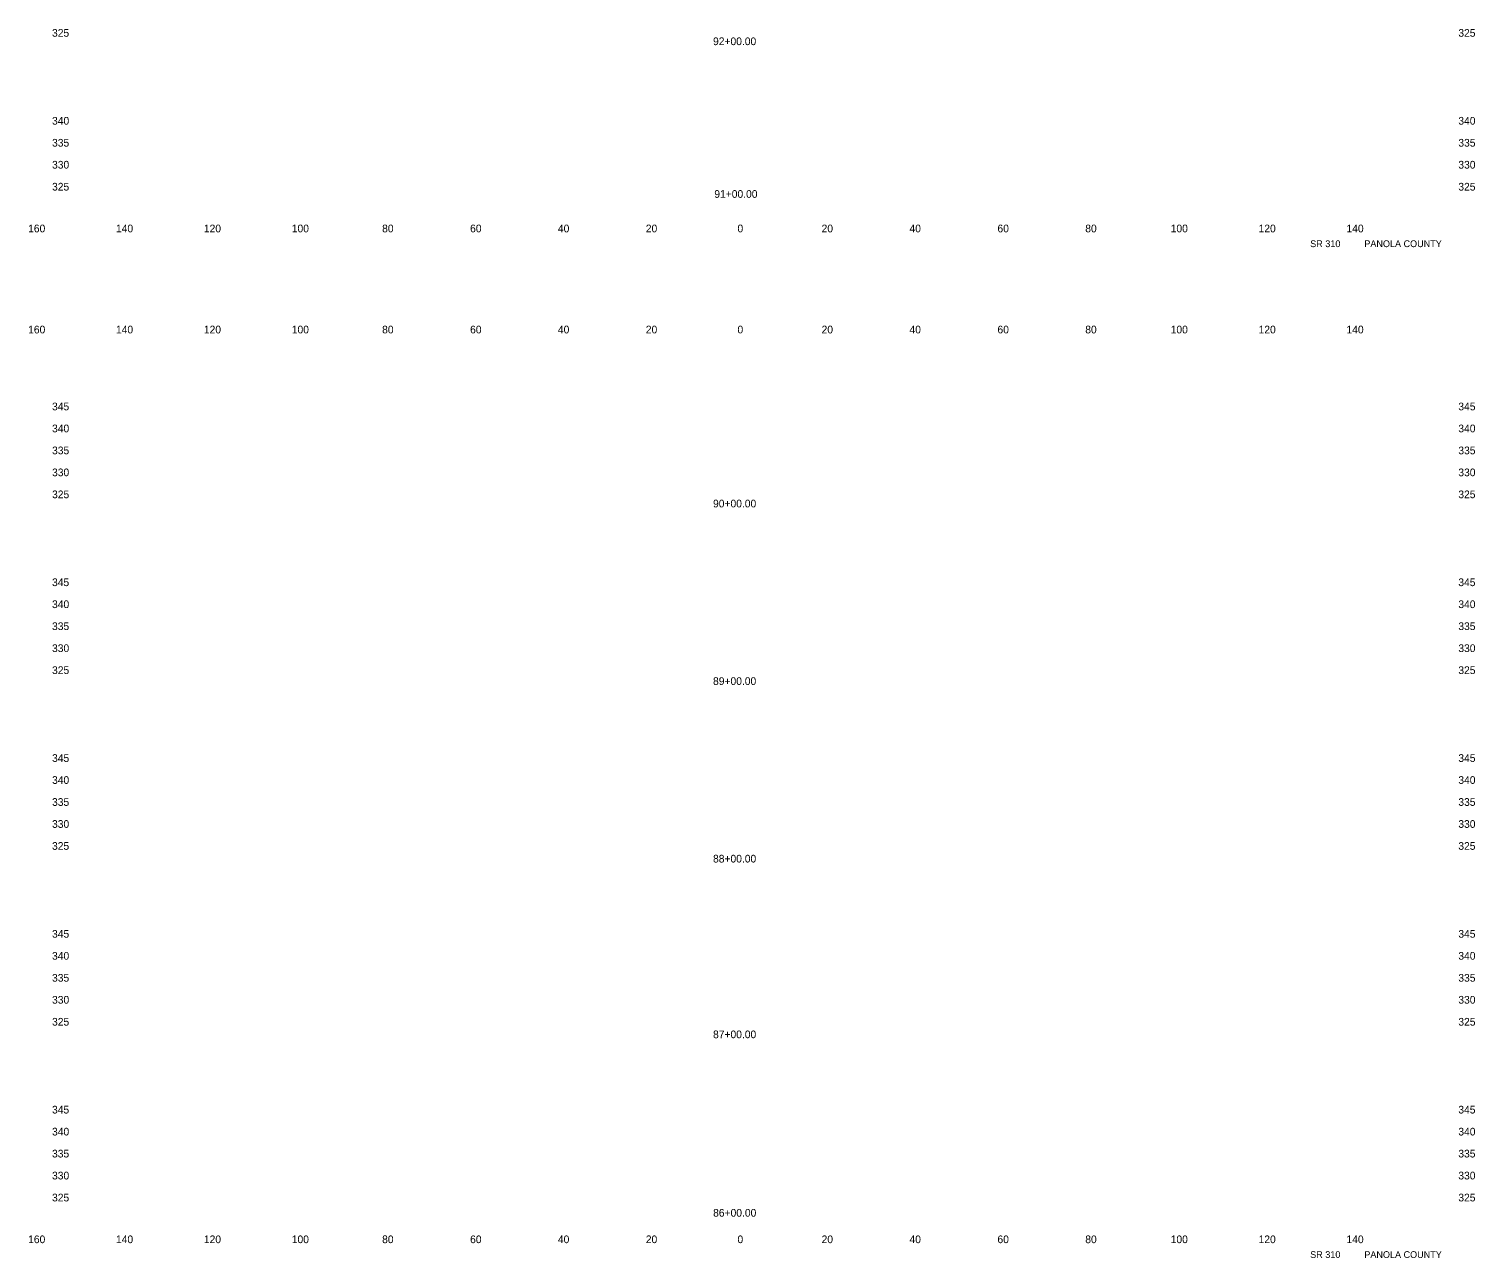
# Model space of a CAD drawing. Extents: x 21481 to 21810, y 6485 to 11067.
# Drawn here: x 21480.9 to 21809.9, y 6484.8 to 6764.5 of the extents above; entities that cross this region are included whole.
import ezdxf

# ---------------------------------------------------------------- set-up
doc = ezdxf.new("R2010")
doc.units = 0
for name, color, linetype in [('62', 7, 'Continuous'), ('XS_CELL', 7, 'Continuous'), ('XS_P_TX_DCH', 7, 'Continuous'), ('XS_P_TX_FS_BS', 7, 'Continuous')]:
    doc.layers.add(name, color=color, linetype=linetype)

msp = doc.modelspace()

# ---------------------------------------------------------------- texts
at = {"layer": '62'}
for s, p in [('  160  ', (21479.4, 6718.21)), ('  140  ', (21499.39, 6718.21)), ('  120  ', (21519.39, 6718.21)), ('  100  ', (21539.39, 6718.21)), ('  80  ', (21559.95, 6718.21)), ('  60  ', (21579.97, 6718.21)), ('  40  ', (21599.95, 6718.21)), ('  20  ', (21619.95, 6718.21)), ('  0  ', (21640.81, 6718.21)), ('  0  ', (21640.81, 6718.21)), ('  20  ', (21659.95, 6718.21)), ('  40  ', (21679.95, 6718.21)), ('  60  ', (21699.97, 6718.21)), ('  80  ', (21719.95, 6718.21)), ('  100  ', (21739.39, 6718.21)), ('  120  ', (21759.39, 6718.21)), ('  140  ', (21779.39, 6718.21)), ('  160  ', (21479.4, 6695.21)), ('  140  ', (21499.39, 6695.21)), ('  120  ', (21519.39, 6695.21)), ('  100  ', (21539.39, 6695.21)), ('  80  ', (21559.95, 6695.21)), ('  60  ', (21579.97, 6695.21)), ('  40  ', (21599.95, 6695.21)), ('  20  ', (21619.95, 6695.21)), ('  0  ', (21640.81, 6695.21)), ('  0  ', (21640.81, 6695.21)), ('  20  ', (21659.95, 6695.21)), ('  40  ', (21679.95, 6695.21)), ('  60  ', (21699.97, 6695.21)), ('  80  ', (21719.95, 6695.21)), ('  100  ', (21739.39, 6695.21)), ('  120  ', (21759.39, 6695.21)), ('  140  ', (21779.39, 6695.21)), ('  160  ', (21479.4, 6488.21)), ('  140  ', (21499.39, 6488.21)), ('  120  ', (21519.39, 6488.21)), ('  100  ', (21539.39, 6488.21)), ('  80  ', (21559.95, 6488.21)), ('  60  ', (21579.97, 6488.21)), ('  40  ', (21599.95, 6488.21)), ('  20  ', (21619.95, 6488.21)), ('  0  ', (21640.81, 6488.21)), ('  0  ', (21640.81, 6488.21)), ('  20  ', (21659.95, 6488.21)), ('  40  ', (21679.95, 6488.21)), ('  60  ', (21699.97, 6488.21)), ('  80  ', (21719.95, 6488.21)), ('  100  ', (21739.39, 6488.21)), ('  120  ', (21759.39, 6488.21)), ('  140  ', (21779.39, 6488.21))]:
    msp.add_text(s, height=1.75, dxfattribs=at).set_placement(p)
at = {"layer": 'XS_CELL'}
for s, p in [('  325  ', (21484.84, 6762.71)), ('  325  ', (21804.84, 6762.71)), ('  340  ', (21484.84, 6742.71)), ('  340  ', (21804.84, 6742.71)), ('  335  ', (21484.84, 6737.71)), ('  335  ', (21804.84, 6737.71)), ('  330  ', (21484.84, 6732.71)), ('  330  ', (21804.84, 6732.71)), ('  325  ', (21484.84, 6727.71)), ('  325  ', (21804.84, 6727.71)), ('  345  ', (21484.84, 6677.71)), ('  345  ', (21804.84, 6677.71)), ('  340  ', (21484.84, 6672.71)), ('  340  ', (21804.84, 6672.71)), ('  335  ', (21484.84, 6667.71)), ('  335  ', (21804.84, 6667.71)), ('  330  ', (21484.84, 6662.71)), ('  330  ', (21804.84, 6662.71)), ('  325  ', (21484.84, 6657.71)), ('  325  ', (21804.84, 6657.71)), ('  345  ', (21484.84, 6637.71)), ('  345  ', (21804.84, 6637.71)), ('  340  ', (21484.84, 6632.71)), ('  340  ', (21804.84, 6632.71)), ('  335  ', (21484.84, 6627.71)), ('  335  ', (21804.84, 6627.71)), ('  330  ', (21484.84, 6622.71)), ('  330  ', (21804.84, 6622.71)), ('  325  ', (21484.84, 6617.71)), ('  325  ', (21804.84, 6617.71)), ('  345  ', (21484.84, 6597.71)), ('  345  ', (21804.84, 6597.71)), ('  340  ', (21484.84, 6592.71)), ('  340  ', (21804.84, 6592.71)), ('  335  ', (21484.84, 6587.71)), ('  335  ', (21804.84, 6587.71)), ('  330  ', (21484.84, 6582.71)), ('  330  ', (21804.84, 6582.71)), ('  325  ', (21484.84, 6577.71)), ('  325  ', (21804.84, 6577.71)), ('  345  ', (21484.84, 6557.71)), ('  345  ', (21804.84, 6557.71)), ('  340  ', (21484.84, 6552.71)), ('  340  ', (21804.84, 6552.71)), ('  335  ', (21484.84, 6547.71)), ('  335  ', (21804.84, 6547.71)), ('  330  ', (21484.84, 6542.71)), ('  330  ', (21804.84, 6542.71)), ('  325  ', (21484.84, 6537.71)), ('  325  ', (21804.84, 6537.71)), ('  345  ', (21484.84, 6517.71)), ('  345  ', (21804.84, 6517.71)), ('  340  ', (21484.84, 6512.71)), ('  340  ', (21804.84, 6512.71)), ('  335  ', (21484.84, 6507.71)), ('  335  ', (21804.84, 6507.71)), ('  330  ', (21484.84, 6502.71)), ('  330  ', (21804.84, 6502.71)), ('  325  ', (21484.84, 6497.71)), ('  325  ', (21804.84, 6497.71))]:
    msp.add_text(s, height=1.75, dxfattribs=at).set_placement(p)
at = {"layer": 'XS_P_TX_DCH'}
for s, p in [('  92+00.00  ', (21635.25, 6760.8)), ('  91+00.00  ', (21635.54, 6726.06)), ('  90+00.00  ', (21635.25, 6655.62)), ('  89+00.00  ', (21635.25, 6615.22)), ('  88+00.00  ', (21635.25, 6574.82)), ('  87+00.00  ', (21635.25, 6534.84)), ('  86+00.00  ', (21635.27, 6494.24))]:
    msp.add_text(s, height=1.75, dxfattribs=at).set_placement(p)
at = {"layer": 'XS_P_TX_FS_BS'}
for s, p in [('SR 310', (21772.43, 6714.84)), ('SR 310', (21772.43, 6714.84)), ('PANOLA COUNTY', (21784.75, 6714.84)), ('PANOLA COUNTY', (21784.75, 6714.84)), ('SR 310', (21772.43, 6484.84)), ('PANOLA COUNTY', (21784.75, 6484.84))]:
    msp.add_text(s, height=1.54, dxfattribs=at).set_placement(p)

doc.saveas('drawing.dxf')
